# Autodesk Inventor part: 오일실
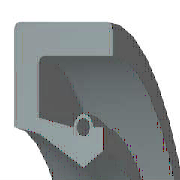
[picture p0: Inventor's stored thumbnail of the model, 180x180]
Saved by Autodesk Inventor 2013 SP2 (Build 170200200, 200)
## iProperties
IsCustomPart: 0
Created: 2009-02
Part Number: 오일실
Material: 고무
Description: 오일-실
Document SubType Name: Modeling
Standard: KS B 2804
Standards Organization: KS
Language: ko-KR
Size Designation: S - 17 30 8
Categories: <MemberInstance><Categories><Category DisplayName="샤프트 부품" InternalName="7f7aeb1f-a693-4053-b835-cee3144e0d98" Mnemonic="SHFT"><Category DisplayName="실링" Intern
Density: 0.93 g/cm^3
Author: pww
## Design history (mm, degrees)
revolve "본체" stored, may be unused: angle "d17" = 90 deg
revolve "스프링1" stored, may be unused: angle "d18" = 90 deg
body "Solid1"
sketch "스케치1"
  geometry: L1 (0, 15)-(8, 15); L2 (8, 15)-(8, 13.75); L3 (8, 13.75)-(1.75, 13.75); L4 (0, 15)-(0, 10.6); L5 (0, 10.6)-(1.75, 10.25); L6 (1.75, 10.25)-(4.9, 8.5); L7 (4.9, 8.5)-(0, 8.5); L8 (6.3, 9.375)-(6.3, 10.6); L9 (0, 0)-(9.586, 0) reference; L10 (4.9, 8.5)-(6.3, 9.375); L11 (0, 18)-(0, -3) reference; L12 (-1.917, 0)-(11.503, 0) reference; L13 (4.2, 10.6)-(1.75, 11.09); L14 (1.75, 11.09)-(1.75, 13.75); L15 (6.3, 10.6)-(5.6, 10.6); C1 r 0.455 at (4.9, 10.6); A1 r 0.7 centre (4.9, 10.6) between (5.6, 10.6) and (4.2, 10.6)
  constraints: 26 end point, 5 horizontal alignment, 4 perpendicular, 2 centre point, 2 collinear, 2 horizontal, 2 parallel, 2 point on circle, 2 point on line, 2 vertical alignment, 1 coincident
  dimensions: "d0" = 30 diameter of L1 L9 (= SD2); "d1" = 18.75 diameter of L8.start L9 (= ABDM); "d2" = 1.25 distance of L1.end L2.end (computed from SD); "d3" = 0.91 diameter of C1 (= SPDI); "d4" = 1.4 diameter of A1 (= SPDA); "d5" = 17 diameter of L6.end L9 (= NND); "d6" = 20.5 diameter of L5.end L9 (= TKDM); "d7" = 21.2 diameter of L4.end L9 (= HLDM); "d8" = 4.9 distance from line of C1.centre L4 (= SPDST); "d9" = 6.3 distance between parallel lines of L8 L4 (= SDI); "d10" = 8 distance between parallel lines of L2 L4 (= SWDT); "d12" = 1.75 distance between parallel lines of L14 L4 (= SD)
fillet "모깎기1" dims "d11" = 0.3 (= RR)
other parameters: "SD2" = 30 [user parameter; used in 1 equation term], "SWDT" = 8 [user parameter; used in 1 equation term], "RR" = 0.3 [user parameter; used in 1 equation term], "SD" = 1.75 [user parameter; used in 2 equation terms], "NND" = 17 [user parameter; used in 1 equation term], "SPDA" = 1.4 [user parameter; used in 1 equation term], "SPDI" = 0.91 [user parameter; used in 1 equation term], "TKDM" = 20.5 [user parameter; used in 1 equation term], "HLDM" = 21.2 [user parameter; used in 1 equation term], "ABDM" = 18.75 [user parameter; used in 1 equation term], "SDI" = 6.3 [user parameter; used in 1 equation term], "SPDST" = 4.9 [user parameter; used in 1 equation term], "d13" = 0, "d14" = 0, "d15" = 0, "LAB" = 0.35 [user parameter]
